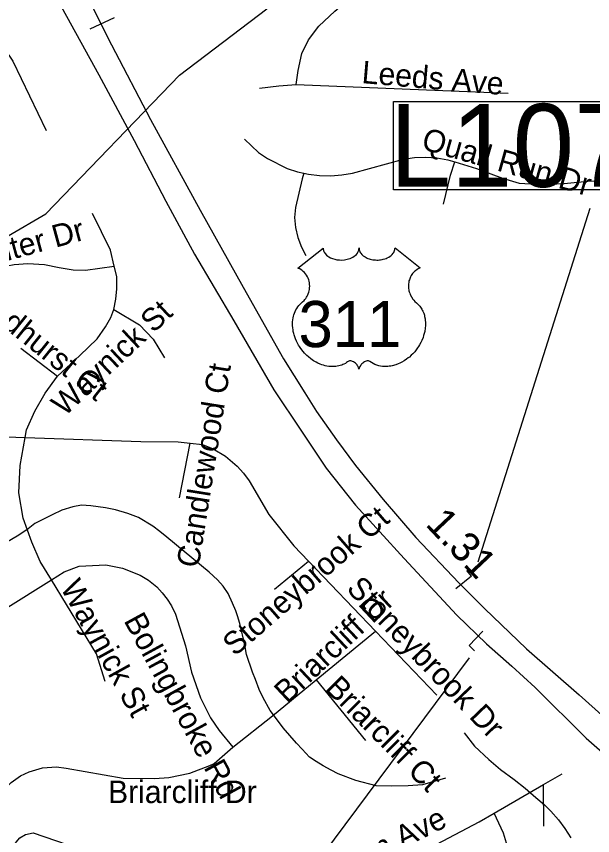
# Model space of a CAD drawing. Extents: x 1662474 to 1856135, y 779280 to 917889.
# Drawn here: x 1707230 to 1709665, y 816221 to 819682 of the extents above; entities that cross this region are included whole.
import ezdxf

# ---------------------------------------------------------------- set-up
doc = ezdxf.new("R2010")
doc.units = 0
for name, color, linetype in [('Exist Hydrographic Misc Water Feature', 7, 'Continuous'), ('Exist Road Non-System Type 51', 7, 'Continuous'), ('Exist Road Non-System Type 51 Label', 7, 'Continuous'), ('Exist Road Primary US Divided Attributed', 7, 'Continuous'), ('Exist Road Primary US Mileage Hundredths English Label', 7, 'Continuous'), ('Exist Road Primary US Shield CELL', 7, 'Continuous'), ('Exist Road Primary US Shield Number Label', 7, 'Continuous'), ('Exist Road Primary US Structure Cantilever Sign CELL', 7, 'Continuous'), ('Exist Road Primary US Structure Cantilever Sign Number Label', 7, 'Continuous'), ('Exist Road Primary US Structure Ovrhead Sign CELL', 7, 'Continuous')]:
    doc.layers.add(name, color=color, linetype=linetype)

msp = doc.modelspace()

# ---------------------------------------------------------------- linework, layer by layer
at = {"layer": 'Exist Hydrographic Misc Water Feature'}
for points in [[(1705403.1, 817006.2), (1705899.1, 817468.7), (1706161.1, 817808), (1706280.1, 818038.8), (1706591.2, 818311.4), (1706734.1, 818495.6), (1706794.2, 818625.6), (1706870.2, 818693.1), (1707195.2, 818755.4), (1707354.2, 818847.4), (1707919.2, 819433.2), (1708288.2, 819714.6), (1708465.1, 819960.4), (1708625.2, 820118.1), (1708860.2, 820274.1), (1709089.8, 820345.3), (1709286.2, 820386.9)], [(1709044.2, 816464.4), (1708945.9, 816435.4), (1708885.8, 816431.9), (1708813.8, 816430.7), (1708749.8, 816431.2), (1708664, 816454.1), (1708590.3, 816482.7), (1708560.4, 816497.1), (1708526.6, 816515.4), (1708496.6, 816533.6), (1708468.9, 816551.9), (1708437.2, 816586.3), (1708413.4, 816612.4), (1708358, 816677), (1708320.4, 816725.4), (1708302.6, 816749.6), (1708273.1, 816803.9), (1708255.6, 816838.1), (1708239.9, 816880.2), (1708228.1, 816912.3), (1708202.9, 816986.6), (1708195.3, 817026.6), (1708174.2, 817116.9), (1708164.4, 817149.1), (1708156.6, 817171.1), (1708142.9, 817203.2), (1708125.3, 817243.4), (1708103.6, 817275.6), (1708080, 817301.9), (1708044.2, 817334.2), (1707865.4, 817482), (1707835.6, 817506.3), (1707805.9, 817528.6), (1707746.2, 817565.1), (1707700.4, 817581.6), (1707648.5, 817598.1), (1707606.5, 817606.4), (1707544.7, 817615), (1707504.7, 817617.4), (1707468.5, 817609.8), (1707422.4, 817596.2), (1707380.3, 817576.6), (1707307.7, 817539.2), (1707279.6, 817517.5), (1707239.3, 817489.9), (1707160.9, 817444.6)], [(1709122, 816655.8), (1709165.5, 816599.4), (1709227, 816542.8), (1709276.6, 816500.3), (1709334.3, 816457.7), (1709379.9, 816421.3), (1709425.5, 816382.8), (1709461.3, 816352.5), (1709489.1, 816324.2), (1709520.7, 816287.9), (1709548.3, 816251.6), (1709574, 816211.4)]]:
    msp.add_lwpolyline(points, dxfattribs=at)
at = {"layer": 'Exist Road Non-System Type 51'}
for p, q in [((1708412.4, 819394.1), (1709309, 819357.4)), ((1707248.9, 818280.4), (1707404, 818162.4)), ((1706897.2, 817915.6), (1707266.5, 817902.8)), ((1707919.2, 817647.9), (1707964.9, 817878.6)), ((1708320.6, 817262.6), (1708464.6, 817380.8)), ((1708464.6, 817380.8), (1708747.9, 817084.2)), ((1708496.6, 816878.7), (1708747.9, 817084.2)), ((1708747.9, 817084.2), (1709007.1, 816813.9)), ((1708496.6, 816878.7), (1708705.1, 816623)), ((1709458.1, 816436.9), (1709536.5, 816482.6)), ((1709249.6, 816315.7), (1709458.1, 816436.9)), ((1709459.9, 816261.1), (1709458.1, 816436.9))]:
    msp.add_line(p, q, dxfattribs=at)
for points in [[(1708412.4, 819394.1), (1708420.2, 819453.4), (1708436.2, 819525.4), (1708464.4, 819582.5), (1708508.5, 819640.8), (1708575.9, 819703.5), (1708949.9, 820025), (1708982.8, 820068.6), (1708985.9, 820076.2)], [(1706405.4, 819663.6), (1706964.9, 819639.5), (1707019.8, 819631.1), (1707070.6, 819615.1), (1707108.5, 819597.2), (1707143.1, 819574.9), (1707179.6, 819544.4), (1707214.8, 819493), (1707356, 819200.1)], [(1708257, 819378.4), (1708338.4, 819388.6), (1708412.4, 819394.1)], [(1708194.6, 819163.2), (1708253.6, 819106.9), (1708290.9, 819081.1), (1708374.9, 819039.6), (1708418.6, 819025.2), (1708444.9, 819019.4)], [(1708444.9, 819019.4), (1708464.4, 819015.1), (1708511.1, 819009.4), (1708558.2, 819008.4), (1708605.2, 819012), (1708650.6, 819020), (1708865.5, 819078.9), (1708912.9, 819086.2), (1708960.2, 819088), (1709007.6, 819084.6), (1709053.4, 819075.9), (1709082.8, 819067.1)], [(1709034.9, 818889.2), (1709064, 819011.2), (1709082.8, 819067.1)], [(1709082.8, 819067.1), (1709174.8, 819039.6), (1709284.4, 818998.2), (1709355.6, 818978.1), (1709450.1, 818971.5), (1709544.6, 818976.2), (1709644.6, 818985.9), (1709722.6, 818987.5), (1709814.2, 818977.2), (1709854.1, 818972)], [(1708444.9, 819019.4), (1708437.6, 818995.1), (1708410.1, 818874.5), (1708405.9, 818833), (1708409.6, 818790), (1708419.6, 818747.4), (1708435, 818706.8), (1708453.1, 818671.5)], [(1707642.9, 818627.4), (1707627.9, 818694.9), (1707551.8, 818849.4)], [(1706844.8, 818510.1), (1706885.1, 818523.2), (1706934.5, 818538.7), (1707001.1, 818566.8), (1707064.6, 818593.2), (1707119.8, 818612.8), (1707161.2, 818623.2), (1707219.8, 818633.4), (1707278.1, 818637.7), (1707347.9, 818634.5), (1707410.4, 818621.1), (1707469.6, 818611.7), (1707521.6, 818609.4), (1707642.9, 818627.4)], [(1707641.6, 818443.9), (1707649.9, 818487.5), (1707654.6, 818531.4), (1707653.9, 818583.6), (1707642.9, 818627.4)], [(1707404, 818162.4), (1707498, 818249.2), (1707571.8, 818320.4), (1707606.1, 818370.8), (1707628.9, 818409.6), (1707641.6, 818443.9)], [(1707641.6, 818443.9), (1707749.9, 818378.6), (1707808.2, 818318), (1707856, 818239.8)], [(1707266.5, 817902.8), (1707272.5, 817935.6), (1707307.6, 818014.9), (1707351, 818090.9), (1707404, 818162.4)], [(1707377.5, 817301.4), (1707330, 817379.2), (1707294.6, 817461.2), (1707258.4, 817562.6), (1707239.5, 817669.4), (1707245, 817784.7), (1707266.5, 817902.8)], [(1707266.5, 817902.8), (1707755.1, 817885.9), (1707912.9, 817884.7), (1707964.9, 817878.6)], [(1707964.9, 817878.6), (1708016.4, 817873.1), (1708061.2, 817854.5), (1708112.9, 817824.5), (1708163.4, 817781.8), (1708189.9, 817752.1), (1708213.1, 817720.1), (1708297.4, 817577.4), (1708402.6, 817445.6), (1708464.6, 817380.8)], [(1707377.5, 817301.4), (1707431.6, 817335.1), (1707494.6, 817359.4), (1707607.1, 817365.2), (1707678.6, 817351.6), (1707752.6, 817321.4), (1707788, 817299.9), (1707822.9, 817271.5), (1707846.5, 817247.1), (1707867.2, 817220.4), (1707885.1, 817191.8), (1707901.9, 817156.1), (1707944.4, 817023), (1707969.6, 816911.2), (1708008.2, 816803.4), (1708050.5, 816718.5), (1708087.2, 816665), (1708144.9, 816595.4)], [(1707141.6, 817162.9), (1707182.2, 817178.9), (1707377.5, 817301.4)], [(1707605.1, 816872.1), (1707568.4, 816989.7), (1707377.5, 817301.4)], [(1708144.9, 816595.4), (1708312.1, 816727.2), (1708496.6, 816878.7)], [(1707073.4, 816147.9), (1707119.2, 816315.7), (1707133.9, 816352.7), (1707148.6, 816378.4), (1707172.2, 816410.4), (1707207.1, 816445.4), (1707247.6, 816473.7), (1707283.2, 816491), (1707340.5, 816507.5), (1707399.9, 816511.2), (1707439.4, 816506.8), (1707680.4, 816464.5), (1707814, 816462.6), (1707873.9, 816466.9), (1707962.6, 816484.9), (1708047.1, 816516.7), (1708065.9, 816526.2), (1708144.9, 816595.4)], [(1709007.1, 816184.9), (1709186.4, 816278.9), (1709249.6, 816315.7)], [(1709411.4, 815524.1), (1709305, 816175.5), (1709289.2, 816231.7), (1709249.6, 816315.7)], [(1707183.6, 816125.9), (1707200.1, 816152.4), (1707207.4, 816169.8), (1707229, 816192.9), (1707244.8, 816211.8), (1707267.6, 816225.9), (1707300.9, 816232.7), (1707543.4, 816149.2)]]:
    msp.add_lwpolyline(points, dxfattribs=at)
at = {"layer": 'Exist Road Primary US Divided Attributed'}
for points in [[(1707219.7, 820103.2), (1707404.1, 819753.3), (1707578.1, 819435.4), (1707727.2, 819157.1), (1707861.4, 818902.1), (1707983.2, 818678.2), (1708148.2, 818395.5), (1708317.2, 818104.9), (1708435.1, 817929.6), (1708539.4, 817773.3), (1708663.8, 817616.9), (1708868.3, 817392.4), (1709091.3, 817152.5), (1709216.8, 817031.2), (1709323.8, 816936.7), (1709422.5, 816846.2), (1709637.5, 816633.5), (1709797.9, 816493.7), (1710089.7, 816236.2), (1710290.6, 816053.2), (1710513.8, 815843.5), (1710670.1, 815705.2), (1710805.1, 815582)], [(1707463.7, 819892.5), (1707545.5, 819731.7), (1707631.3, 819561.8), (1707797.1, 819246), (1708006.1, 818864.1), (1708188.7, 818538), (1708359.3, 818235.9), (1708449.1, 818092.3), (1708498.3, 818012.3), (1708582.4, 817893), (1708663.8, 817784.6), (1708780.4, 817641), (1708918.7, 817481), (1709100.4, 817288.6), (1709208.9, 817180.2), (1709386.5, 817010.8), (1709608.9, 816815.7), (1709839.2, 816608.6), (1710085, 816378.3), (1710296.3, 816174.8), (1710542.1, 815959.9), (1710812.6, 815718.8)]]:
    msp.add_lwpolyline(points, dxfattribs=at)
at = {"layer": 'Exist Road Primary US Shield CELL'}
msp.add_lwpolyline([(1708525.9, 818703.4), (1708526.2, 818699), (1708527.3, 818693.8), (1708528.1, 818691.1), (1708530.6, 818685.9), (1708534.6, 818679.9), (1708540.2, 818673.9), (1708546.5, 818668.7), (1708550.8, 818665.9), (1708558, 818662), (1708566.3, 818658.6), (1708575.4, 818655.9), (1708584.8, 818654), (1708595, 818652.9), (1708605.1, 818652.7), (1708616, 818653.5), (1708628.1, 818655.9), (1708633.7, 818657.3), (1708639.9, 818659.4), (1708645.7, 818661.8), (1708652, 818665.2), (1708657.1, 818668.5), (1708661.1, 818671.4), (1708666.7, 818676.8), (1708671.2, 818682.4), (1708673.1, 818685.5), (1708674.7, 818688.5), (1708677, 818694.9), (1708677.6, 818697.8), (1708678, 818703.6), (1708678.4, 818698.7), (1708678.9, 818695.6), (1708679.7, 818692.6), (1708681, 818689.4), (1708683.2, 818684.9), (1708685.7, 818681.1), (1708690.5, 818675.5), (1708693.4, 818672.8), (1708696.1, 818670.6), (1708703.4, 818665.6), (1708711.8, 818661.3), (1708715.9, 818659.5), (1708720.2, 818658), (1708725.6, 818656.4), (1708731.2, 818655.1), (1708736.7, 818654.1), (1708742.4, 818653.3), (1708748.1, 818652.9), (1708752.8, 818652.7), (1708758.6, 818652.8), (1708764, 818653.1), (1708769.4, 818653.7), (1708775.4, 818654.7), (1708780.3, 818655.8), (1708786.7, 818657.5), (1708792.5, 818659.6), (1708797.5, 818661.8), (1708804.1, 818665.2), (1708809.5, 818668.6), (1708813.4, 818671.7), (1708818, 818676), (1708822.4, 818681.1), (1708825, 818684.8), (1708826.8, 818688.6), (1708828.5, 818692.6), (1708829.5, 818696.9), (1708830, 818700.6), (1708830.1, 818703.7), (1708936.4, 818619.1), (1708933.9, 818618.1), (1708928.1, 818615.3), (1708923.5, 818612.6), (1708916.2, 818607.4), (1708913.1, 818604.6), (1708909.9, 818601.7), (1708907.1, 818598.5), (1708904.5, 818595.6), (1708901.4, 818591.3), (1708898.7, 818587), (1708896, 818582.3), (1708894, 818578.2), (1708890.7, 818569.7), (1708889.2, 818564.3), (1708888.2, 818559.7), (1708886.9, 818550.2), (1708886.6, 818545.7), (1708886.6, 818541.3), (1708886.8, 818536.5), (1708887.3, 818532), (1708888.1, 818527.3), (1708888.9, 818523.2), (1708890.2, 818518.1), (1708892.1, 818512.2), (1708894.4, 818506.5), (1708899.2, 818497.2), (1708905.5, 818487.8), (1708909.9, 818482.5), (1708914.3, 818478), (1708920.9, 818472.5), (1708924.4, 818469.4), (1708928.5, 818465.3), (1708935.2, 818457.5), (1708937.9, 818453.9), (1708940.6, 818449.8), (1708943.1, 818445.6), (1708945.6, 818441.1), (1708947.6, 818437.1), (1708951.4, 818428), (1708954.1, 818419.2), (1708955.4, 818414.5), (1708957.3, 818404.1), (1708958.1, 818399), (1708958.9, 818388.8), (1708958.9, 818376.5), (1708958, 818364.8), (1708955.8, 818351.2), (1708954, 818343), (1708951.2, 818333.5), (1708948.5, 818325.3), (1708943.6, 818313.2), (1708939.3, 818304.4), (1708933.7, 818294.1), (1708929.9, 818287.9), (1708925.4, 818281.2), (1708919.9, 818273.5), (1708913.3, 818265.4), (1708905.5, 818256.8), (1708899.1, 818250.4), (1708890.9, 818243), (1708885.8, 818238.9), (1708878.7, 818233.5), (1708868.9, 818226.9), (1708859.2, 818221.4), (1708851, 818217.2), (1708843.7, 818214), (1708834.3, 818210.4), (1708818.6, 818206.1), (1708812.9, 818204.9), (1708806.1, 818203.9), (1708799.8, 818203.3), (1708793.6, 818202.9), (1708785.4, 818202.9), (1708777.1, 818203.5), (1708769.4, 818204.7), (1708761.3, 818206.4), (1708752.8, 818208.9), (1708745.1, 818211.9), (1708737.3, 818215.7), (1708724.2, 818224), (1708720.4, 818226), (1708718.2, 818226.6), (1708713.1, 818226.8), (1708708.4, 818225.8), (1708703.5, 818223.9), (1708700.5, 818222.3), (1708696.6, 818219.7), (1708693.6, 818217.3), (1708690, 818213.9), (1708687.4, 818211), (1708685.5, 818208.7), (1708681.8, 818202.9), (1708680.5, 818200.1), (1708679.1, 818196.6), (1708677.9, 818191.3), (1708676.2, 818197.9), (1708674.3, 818202.3), (1708672, 818206.1), (1708669.7, 818209.4), (1708666, 818213.7), (1708662.6, 818216.9), (1708658.6, 818220.2), (1708654.4, 818222.7), (1708650.9, 818224.5), (1708647.8, 818225.7), (1708644, 818226.6), (1708640.8, 818226.9), (1708638.3, 818226.8), (1708634.7, 818226), (1708629.9, 818222.6), (1708625.4, 818219.4), (1708620.4, 818216.3), (1708614.5, 818213.2), (1708610.2, 818211.2), (1708605, 818209.2), (1708599, 818207.2), (1708592.5, 818205.5), (1708585.8, 818204.2), (1708579.9, 818203.2), (1708573.5, 818202.6), (1708567.8, 818202.5), (1708561.8, 818202.5), (1708556.3, 818203), (1708549.8, 818203.5), (1708541.8, 818204.7), (1708535.1, 818206.2), (1708528.1, 818208.1), (1708520.9, 818210.4), (1708513.1, 818213.3), (1708503.5, 818217.5), (1708496.8, 818221), (1708486.2, 818227.1), (1708473.7, 818235.7), (1708464.3, 818243.3), (1708457.5, 818249.5), (1708447.4, 818259.8), (1708441.4, 818266.5), (1708432.1, 818278.6), (1708426.1, 818287.3), (1708422.3, 818293.7), (1708416.6, 818304), (1708413.5, 818310.5), (1708409.5, 818319.9), (1708406.3, 818328.5), (1708403.7, 818336.7), (1708402.3, 818341.9), (1708400.3, 818351), (1708399.1, 818357.4), (1708397.9, 818366.3), (1708397.2, 818375.7), (1708397.1, 818384.3), (1708397.3, 818391.4), (1708398.1, 818399.8), (1708399.5, 818408.6), (1708401.2, 818416.2), (1708402.8, 818421.7), (1708405, 818428.3), (1708408, 818435.7), (1708411.5, 818442.7), (1708414.9, 818448.6), (1708419.1, 818454.8), (1708423.2, 818460.2), (1708428.7, 818466.1), (1708434.3, 818471.5), (1708439.5, 818475.7), (1708445.6, 818481.7), (1708448.8, 818485.4), (1708452.7, 818490.5), (1708455.8, 818495.2), (1708458.2, 818499.4), (1708461.5, 818505.6), (1708463.4, 818510.2), (1708465.9, 818517.4), (1708467.1, 818522.4), (1708468.3, 818528.9), (1708469.1, 818535), (1708469.5, 818542.6), (1708469.3, 818548.9), (1708468.5, 818556.2), (1708467.1, 818563.2), (1708465.4, 818569.4), (1708462.8, 818576.4), (1708460.4, 818581.6), (1708456.3, 818588.5), (1708451.8, 818595), (1708447.1, 818600.3), (1708442.4, 818605), (1708437.9, 818608.5), (1708433.6, 818611.6), (1708428.2, 818614.9), (1708422.9, 818617.4), (1708419.7, 818618.7)], close=True, dxfattribs=at)
at = {"layer": 'Exist Road Primary US Structure Cantilever Sign CELL'}
for p, q in [((1709153.9, 817316.8), (1709134.1, 817341.6)), ((1709153.9, 817316.8), (1709087.9, 817264.3)), ((1709143.1, 817024.5), (1709201.9, 817084.9)), ((1709143.1, 817024.5), (1709165.9, 817002.4))]:
    msp.add_line(p, q, dxfattribs=at)
at = {"layer": 'Exist Road Primary US Structure Cantilever Sign Number Label'}
for p, q in [((1709181.6, 817377.3), (1709654.7, 818872.1)), ((1709143.3, 816972.5), (1707785.5, 815151.3))]:
    msp.add_line(p, q, dxfattribs=at)
msp.add_lwpolyline([(1708823.2, 819322.3), (1710352.9, 819322.3), (1710352.9, 818949.1), (1708823.2, 818949.1)], close=True, dxfattribs=at)
at = {"layer": 'Exist Road Primary US Structure Ovrhead Sign CELL'}
msp.add_line((1707541.1, 819628.8), (1707644, 819677.5), dxfattribs=at)

# ---------------------------------------------------------------- texts
at = {"layer": 'Exist Road Non-System Type 51 Label'}
for s, rotation, p in [('Leeds Ave', 355.2014, (1708687.1, 819400.3)), ('Quail Run Dr', 344.1591, (1708937.3, 819122.5)), ('Lassiter Dr', 15.2557, (1706931.8, 818578.1)), ('Sandhurst Ct', 321.3243, (1706988.5, 818516.4)), ('Waynick St', 43.141, (1707433, 817988.8)), ('Candlewood Ct', 80.9303, (1707999.8, 817349.2)), ('Stoneybrook Ct', 40.9878, (1708153.1, 816975.7)), ('Waynick St', 298.894, (1707413.3, 817270)), ('Stoneybrook Dr', 313.8605, (1708620.6, 817260.9)), ('Briarcliff Dr', 43.1686, (1708374.6, 816775.3)), ('Bolingbroke Rd', 298.5855, (1707681.6, 817129.8)), ('Briarcliff Ct', 314.9838, (1708530.1, 816838.8)), ('Wickham Ave', 26.4507, (1708361.5, 815916.6))]:
    msp.add_text(s, height=95, rotation=rotation, dxfattribs=at).set_placement(p)
msp.add_text('Briarcliff Dr', height=95, dxfattribs=at).set_placement((1707617.3, 816358.7))
at = {"layer": 'Exist Road Primary US Mileage Hundredths English Label'}
msp.add_text('1.31', height=125, rotation=313.357, dxfattribs=at).set_placement((1708955, 817533.6))
at = {"layer": 'Exist Road Primary US Shield Number Label'}
msp.add_text('311', height=195, dxfattribs=at).set_placement((1708422.1, 818284.7))
at = {"layer": 'Exist Road Primary US Structure Cantilever Sign Number Label'}
msp.add_text('L1076', height=350, dxfattribs=at).set_placement((1708806.5, 818962))

doc.saveas('drawing.dxf')
